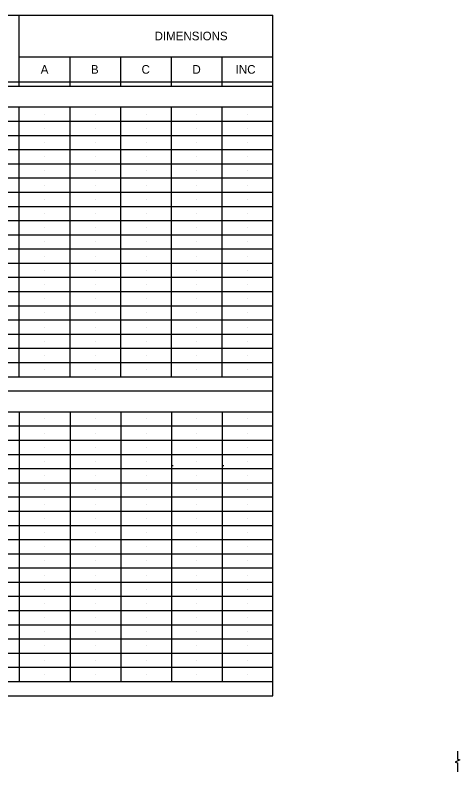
# Model space of a CAD drawing. Extents: x -18.5 to 33.3, y 0.6 to 37.5.
# Drawn here: x 18.57 to 27.34, y 22.61 to 37.54 of the extents above; entities that cross this region are included whole.
import ezdxf

# ---------------------------------------------------------------- set-up
doc = ezdxf.new("R2010")
doc.units = 0
doc.layers.add('BR_X_Beam_Centerline', color=7, linetype='Continuous')

msp = doc.modelspace()

# ---------------------------------------------------------------- linework, layer by layer
at = {"layer": 'BR_X_Beam_Centerline'}
for p, q in [((10.02, 37.539), (23.654, 37.539)), ((18.654, 36.139), (18.654, 37.539)), ((23.654, 24.115), (23.654, 37.539)), ((18.654, 36.715), (23.654, 36.715)), ((19.654, 36.138), (19.654, 36.715)), ((20.654, 36.138), (20.654, 36.715)), ((21.654, 36.138), (21.654, 36.715)), ((22.654, 36.138), (22.654, 36.715)), ((22.654, 36.138), (22.654, 36.715)), ((10.02, 36.221), (23.654, 36.221)), ((10.02, 36.139), (23.654, 36.139)), ((10.02, 35.727), (23.654, 35.727)), ((18.654, 30.407), (18.654, 35.727)), ((19.654, 30.407), (19.654, 35.727)), ((20.654, 30.407), (20.654, 35.727)), ((21.654, 30.407), (21.654, 35.727)), ((22.654, 30.407), (22.654, 35.727)), ((22.654, 30.407), (22.654, 35.727)), ((19.154, 35.587), (19.154, 35.587)), ((20.154, 35.587), (20.154, 35.587)), ((21.154, 35.587), (21.154, 35.587)), ((22.154, 35.587), (22.154, 35.587)), ((23.154, 35.587), (23.154, 35.587)), ((10.02, 35.447), (23.654, 35.447)), ((19.154, 35.307), (19.154, 35.307)), ((20.154, 35.307), (20.154, 35.307)), ((21.154, 35.307), (21.154, 35.307)), ((22.154, 35.307), (22.154, 35.307)), ((23.154, 35.307), (23.154, 35.307)), ((10.02, 35.167), (23.654, 35.167)), ((19.154, 35.027), (19.154, 35.027)), ((20.154, 35.027), (20.154, 35.027)), ((21.154, 35.027), (21.154, 35.027)), ((22.154, 35.027), (22.154, 35.027)), ((23.154, 35.027), (23.154, 35.027)), ((10.02, 34.887), (23.654, 34.887)), ((19.154, 34.747), (19.154, 34.747)), ((20.154, 34.747), (20.154, 34.747)), ((21.154, 34.747), (21.154, 34.747)), ((22.154, 34.747), (22.154, 34.747)), ((23.154, 34.747), (23.154, 34.747)), ((10.02, 34.607), (23.654, 34.607)), ((19.154, 34.467), (19.154, 34.467)), ((20.154, 34.467), (20.154, 34.467)), ((21.154, 34.467), (21.154, 34.467)), ((22.154, 34.467), (22.154, 34.467)), ((23.154, 34.467), (23.154, 34.467)), ((10.02, 34.327), (23.654, 34.327)), ((19.154, 34.187), (19.154, 34.187)), ((20.154, 34.187), (20.154, 34.187)), ((21.154, 34.187), (21.154, 34.187)), ((22.154, 34.187), (22.154, 34.187)), ((23.154, 34.187), (23.154, 34.187)), ((10.02, 34.047), (23.654, 34.047)), ((19.154, 33.907), (19.154, 33.907)), ((20.154, 33.907), (20.154, 33.907)), ((21.154, 33.907), (21.154, 33.907)), ((22.154, 33.907), (22.154, 33.907)), ((23.154, 33.907), (23.154, 33.907)), ((10.02, 33.767), (23.654, 33.767)), ((19.154, 33.627), (19.154, 33.627)), ((20.154, 33.627), (20.154, 33.627)), ((21.154, 33.627), (21.154, 33.627)), ((22.154, 33.627), (22.154, 33.627)), ((23.154, 33.627), (23.154, 33.627)), ((10.02, 33.487), (23.654, 33.487)), ((19.154, 33.347), (19.154, 33.347)), ((20.154, 33.347), (20.154, 33.347)), ((21.154, 33.347), (21.154, 33.347)), ((22.154, 33.347), (22.154, 33.347)), ((23.154, 33.347), (23.154, 33.347)), ((10.02, 33.207), (23.654, 33.207)), ((19.154, 33.067), (19.154, 33.067)), ((20.154, 33.067), (20.154, 33.067)), ((21.154, 33.067), (21.154, 33.067)), ((22.154, 33.067), (22.154, 33.067)), ((23.154, 33.067), (23.154, 33.067)), ((10.02, 32.927), (23.654, 32.927)), ((19.154, 32.787), (19.154, 32.787)), ((20.154, 32.787), (20.154, 32.787)), ((21.154, 32.787), (21.154, 32.787)), ((22.154, 32.787), (22.154, 32.787)), ((23.154, 32.787), (23.154, 32.787)), ((10.02, 32.647), (23.654, 32.647)), ((19.154, 32.507), (19.154, 32.507)), ((20.154, 32.507), (20.154, 32.507)), ((21.154, 32.507), (21.154, 32.507)), ((22.154, 32.507), (22.154, 32.507)), ((23.154, 32.507), (23.154, 32.507)), ((10.02, 32.367), (23.654, 32.367)), ((19.154, 32.227), (19.154, 32.227)), ((20.154, 32.227), (20.154, 32.227)), ((21.154, 32.227), (21.154, 32.227)), ((22.154, 32.227), (22.154, 32.227)), ((23.154, 32.227), (23.154, 32.227)), ((10.02, 32.087), (23.654, 32.087)), ((19.154, 31.947), (19.154, 31.947)), ((20.154, 31.947), (20.154, 31.947)), ((21.154, 31.947), (21.154, 31.947)), ((22.154, 31.947), (22.154, 31.947)), ((23.154, 31.947), (23.154, 31.947)), ((10.02, 31.807), (23.654, 31.807)), ((19.154, 31.667), (19.154, 31.667)), ((20.154, 31.667), (20.154, 31.667)), ((21.154, 31.667), (21.154, 31.667)), ((22.154, 31.667), (22.154, 31.667)), ((23.154, 31.667), (23.154, 31.667)), ((10.02, 31.527), (23.654, 31.527)), ((19.154, 31.387), (19.154, 31.387)), ((20.154, 31.387), (20.154, 31.387)), ((21.154, 31.387), (21.154, 31.387)), ((22.154, 31.387), (22.154, 31.387)), ((23.154, 31.387), (23.154, 31.387)), ((10.02, 31.247), (23.654, 31.247)), ((19.154, 31.107), (19.154, 31.107)), ((20.154, 31.107), (20.154, 31.107)), ((21.154, 31.107), (21.154, 31.107)), ((22.154, 31.107), (22.154, 31.107)), ((23.154, 31.107), (23.154, 31.107)), ((10.02, 30.967), (23.654, 30.967)), ((19.154, 30.827), (19.154, 30.827)), ((20.154, 30.827), (20.154, 30.827)), ((21.154, 30.827), (21.154, 30.827)), ((22.154, 30.827), (22.154, 30.827)), ((23.154, 30.827), (23.154, 30.827)), ((10.02, 30.687), (23.654, 30.687)), ((19.154, 30.547), (19.154, 30.547)), ((20.154, 30.547), (20.154, 30.547)), ((21.154, 30.547), (21.154, 30.547)), ((22.154, 30.547), (22.154, 30.547)), ((23.154, 30.547), (23.154, 30.547)), ((10.02, 30.407), (23.654, 30.407)), ((10.02, 30.127), (23.654, 30.127)), ((10.02, 29.715), (23.654, 29.715)), ((18.654, 29.715), (18.654, 24.395)), ((19.654, 29.715), (19.654, 24.395)), ((20.654, 29.715), (20.654, 24.395)), ((21.654, 29.715), (21.654, 24.395)), ((22.654, 29.715), (22.654, 24.395)), ((22.654, 29.715), (22.654, 24.395)), ((19.154, 29.575), (19.154, 29.575)), ((20.154, 29.575), (20.154, 29.575)), ((21.154, 29.575), (21.154, 29.575)), ((22.154, 29.575), (22.154, 29.575)), ((23.154, 29.575), (23.154, 29.575)), ((10.02, 29.435), (23.654, 29.435)), ((19.154, 29.295), (19.154, 29.295)), ((20.154, 29.295), (20.154, 29.295)), ((21.154, 29.295), (21.154, 29.295)), ((22.154, 29.295), (22.154, 29.295)), ((23.154, 29.295), (23.154, 29.295)), ((10.02, 29.155), (23.654, 29.155)), ((19.154, 29.015), (19.154, 29.015)), ((20.154, 29.015), (20.154, 29.015)), ((21.154, 29.015), (21.154, 29.015)), ((22.154, 29.015), (22.154, 29.015)), ((23.154, 29.015), (23.154, 29.015)), ((10.02, 28.875), (23.654, 28.875)), ((19.154, 28.735), (19.154, 28.735)), ((20.154, 28.735), (20.154, 28.735)), ((21.154, 28.735), (21.154, 28.735)), ((21.684, 28.643), (21.684, 28.659)), ((22.154, 28.735), (22.154, 28.735)), ((22.679, 28.643), (22.679, 28.659)), ((23.154, 28.735), (23.154, 28.735)), ((10.02, 28.595), (23.654, 28.595)), ((19.154, 28.455), (19.154, 28.455)), ((20.154, 28.455), (20.154, 28.455)), ((21.154, 28.455), (21.154, 28.455)), ((22.154, 28.455), (22.154, 28.455)), ((23.154, 28.455), (23.154, 28.455)), ((10.02, 28.315), (23.654, 28.315)), ((19.154, 28.175), (19.154, 28.175)), ((20.154, 28.175), (20.154, 28.175)), ((21.154, 28.175), (21.154, 28.175)), ((22.154, 28.175), (22.154, 28.175)), ((23.154, 28.175), (23.154, 28.175)), ((10.02, 28.035), (23.654, 28.035)), ((19.154, 27.895), (19.154, 27.895)), ((20.154, 27.895), (20.154, 27.895)), ((21.154, 27.895), (21.154, 27.895)), ((22.154, 27.895), (22.154, 27.895)), ((23.154, 27.895), (23.154, 27.895)), ((10.02, 27.755), (23.654, 27.755)), ((19.154, 27.615), (19.154, 27.615)), ((20.154, 27.615), (20.154, 27.615)), ((21.154, 27.615), (21.154, 27.615)), ((22.154, 27.615), (22.154, 27.615)), ((23.154, 27.615), (23.154, 27.615)), ((10.02, 27.475), (23.654, 27.475)), ((19.154, 27.335), (19.154, 27.335)), ((20.154, 27.335), (20.154, 27.335)), ((21.154, 27.335), (21.154, 27.335)), ((22.154, 27.335), (22.154, 27.335)), ((23.154, 27.335), (23.154, 27.335)), ((10.02, 27.195), (23.654, 27.195)), ((19.154, 27.055), (19.154, 27.055)), ((20.154, 27.055), (20.154, 27.055)), ((21.154, 27.055), (21.154, 27.055)), ((22.154, 27.055), (22.154, 27.055)), ((23.154, 27.055), (23.154, 27.055)), ((10.02, 26.915), (23.654, 26.915)), ((19.154, 26.775), (19.154, 26.775)), ((20.154, 26.775), (20.154, 26.775)), ((21.154, 26.775), (21.154, 26.775)), ((22.154, 26.775), (22.154, 26.775)), ((23.154, 26.775), (23.154, 26.775)), ((10.02, 26.635), (23.654, 26.635)), ((19.154, 26.495), (19.154, 26.495)), ((20.154, 26.495), (20.154, 26.495)), ((21.154, 26.495), (21.154, 26.495)), ((22.154, 26.495), (22.154, 26.495)), ((23.154, 26.495), (23.154, 26.495)), ((10.02, 26.355), (23.654, 26.355)), ((19.154, 26.215), (19.154, 26.215)), ((20.154, 26.215), (20.154, 26.215)), ((21.154, 26.215), (21.154, 26.215)), ((22.154, 26.215), (22.154, 26.215)), ((23.154, 26.215), (23.154, 26.215)), ((10.02, 26.075), (23.654, 26.075)), ((19.154, 25.935), (19.154, 25.935)), ((20.154, 25.935), (20.154, 25.935)), ((21.154, 25.935), (21.154, 25.935)), ((22.154, 25.935), (22.154, 25.935)), ((23.154, 25.935), (23.154, 25.935)), ((10.02, 25.795), (23.654, 25.795)), ((19.154, 25.655), (19.154, 25.655)), ((20.154, 25.655), (20.154, 25.655)), ((21.154, 25.655), (21.154, 25.655)), ((22.154, 25.655), (22.154, 25.655)), ((23.154, 25.655), (23.154, 25.655)), ((10.02, 25.515), (23.654, 25.515)), ((19.154, 25.375), (19.154, 25.375)), ((20.154, 25.375), (20.154, 25.375)), ((21.154, 25.375), (21.154, 25.375)), ((22.154, 25.375), (22.154, 25.375)), ((23.154, 25.375), (23.154, 25.375)), ((10.02, 25.235), (23.654, 25.235)), ((19.154, 25.095), (19.154, 25.095)), ((20.154, 25.095), (20.154, 25.095)), ((21.154, 25.095), (21.154, 25.095)), ((22.154, 25.095), (22.154, 25.095)), ((23.154, 25.095), (23.154, 25.095)), ((10.02, 24.955), (23.654, 24.955)), ((19.154, 24.815), (19.154, 24.815)), ((20.154, 24.815), (20.154, 24.815)), ((21.154, 24.815), (21.154, 24.815)), ((22.154, 24.815), (22.154, 24.815)), ((23.154, 24.815), (23.154, 24.815)), ((10.02, 24.675), (23.654, 24.675)), ((19.154, 24.535), (19.154, 24.535)), ((20.154, 24.535), (20.154, 24.535)), ((21.154, 24.535), (21.154, 24.535)), ((22.154, 24.535), (22.154, 24.535)), ((23.154, 24.535), (23.154, 24.535)), ((10.02, 24.395), (23.654, 24.395)), ((10.02, 24.115), (23.654, 24.115))]:
    msp.add_line(p, q, dxfattribs=at)
msp.add_lwpolyline([(27.3, 23.022), (27.3, 22.863), (27.345, 22.848), (27.255, 22.803), (27.3, 22.788), (27.3, 22.612)], dxfattribs=at)

# ---------------------------------------------------------------- texts
for s, p in [('DIMENSIONS', (21.323, 37.042)), ('A', (19.076, 36.383)), ('B', (20.067, 36.383)), ('C', (21.065, 36.383)), ('D', (22.069, 36.383)), ('INC', (22.922, 36.383))]:
    msp.add_text(s, height=0.17, dxfattribs=at).set_placement(p)

doc.saveas('drawing.dxf')
